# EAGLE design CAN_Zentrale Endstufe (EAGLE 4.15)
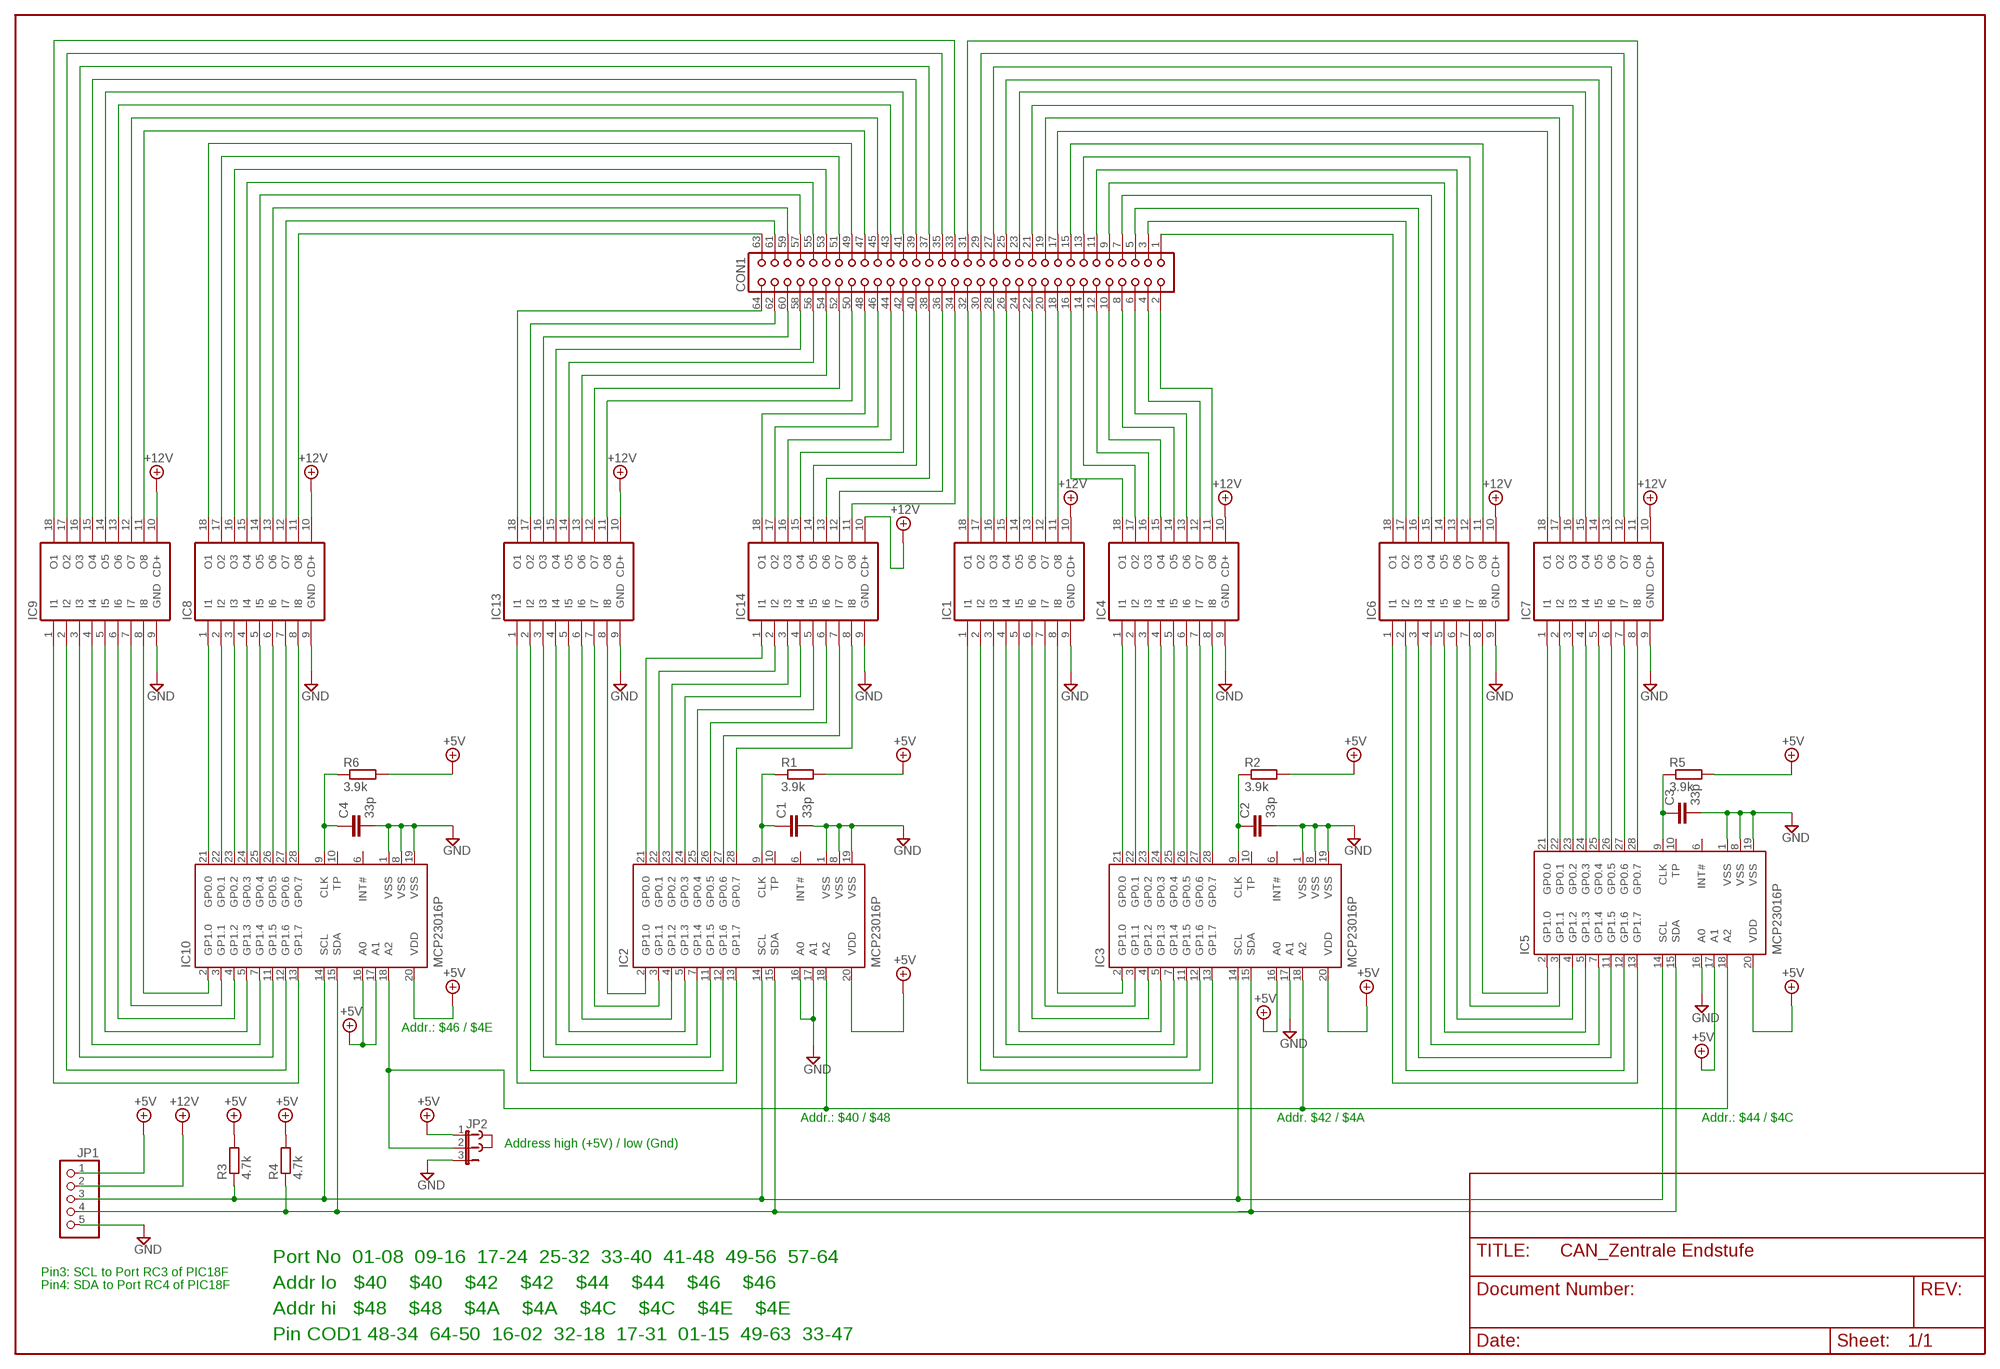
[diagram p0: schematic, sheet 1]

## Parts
C1  33p  C-EU025-025X050  [C025-025X050]
C2  33p  C-EU025-025X050  [C025-025X050]
C3  33p  C-EU025-025X050  [C025-025X050]
C4  33p  C-EU025-025X050  [C025-025X050]
CON1  CON64  [CON64]
IC1  ULN2803A  [DIL18]
IC2  MCP23016P  [DIL28-3]
IC3  MCP23016P  [DIL28-3]
IC4  ULN2803A  [DIL18]
IC5  MCP23016P  [DIL28-3]
IC6  ULN2803A  [DIL18]
IC7  ULN2803A  [DIL18]
IC8  ULN2803A  [DIL18]
IC9  ULN2803A  [DIL18]
IC10  MCP23016P  [DIL28-3]
IC13  ULN2803A  [DIL18]
IC14  ULN2803A  [DIL18]
J2  JUMPER  [JUMP]
JP1  PINHD-1X5  [1X05]
JP2  JP2E  [JP2]
R1  3.9k  R-EU_0204/7  [0204/7]
R2  3.9k  R-EU_0204/7  [0204/7]
R3  4.7k  R-EU_0204/7  [0204/7]
R4  4.7k  R-EU_0204/7  [0204/7]
R5  3.9k  R-EU_0204/7  [0204/7]
R6  3.9k  R-EU_0204/7  [0204/7]

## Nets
+5V: IC2.20(VDD) IC3.16(A0) IC3.20(VDD) IC5.17(A1) IC5.20(VDD) IC10.16(A0) IC10.17(A1) IC10.20(VDD) JP1.1 JP2.1 R1.2 R2.2 R3.2 R4.2 R5.2 R6.2
+12V: IC1.10(CD+) IC4.10(CD+) IC6.10(CD+) IC7.10(CD+) IC8.10(CD+) IC9.10(CD+) IC13.10(CD+) IC14.10(CD+) JP1.2
GND: C1.2 C2.2 C3.2 C4.2 IC1.9(GND) IC2.1(VSS) IC2.8(VSS) IC2.16(A0) IC2.17(A1) IC2.19(VSS) IC3.1(VSS) IC3.8(VSS) IC3.17(A1) IC3.19(VSS) IC4.9(GND) IC5.1(VSS) IC5.8(VSS) IC5.16(A0) IC5.19(VSS) IC6.9(GND) IC7.9(GND) IC8.9(GND) IC9.9(GND) IC10.1(VSS) IC10.8(VSS) IC10.19(VSS) IC13.9(GND) IC14.9(GND) JP1.5 JP2.3
N$1: IC2.28(GP0.7) IC14.8(I8)
N$2: IC2.27(GP0.6) IC14.7(I7)
N$3: IC2.26(GP0.5) IC14.6(I6)
N$4: IC2.25(GP0.4) IC14.5(I5)
N$5: IC2.24(GP0.3) IC14.4(I4)
N$6: IC2.23(GP0.2) IC14.3(I3)
N$7: IC2.22(GP0.1) IC14.2(I2)
N$8: C1.1 IC2.9(CLK) R1.1
N$9: IC2.21(GP0.0) IC14.1(I1)
N$10: IC2.2(GP1.0) IC13.8(I8)
N$11: IC2.3(GP1.1) IC13.7(I7)
N$12: IC2.4(GP1.2) IC13.6(I6)
N$13: IC2.5(GP1.3) IC13.5(I5)
N$14 [thick]: CON1.32 IC1.18(O1)
N$15: IC2.11(GP1.5) IC13.3(I3)
N$16: IC2.12(GP1.6) IC13.2(I2)
N$17: IC2.13(GP1.7) IC13.1(I1)
N$18 [thick]: CON1.50 IC13.11(O8)
N$19: IC2.15(SDA) IC3.15(SDA) IC5.15(SDA) IC10.15(SDA) JP1.4 R4.1
N$20 [thick]: CON1.52 IC13.12(O7)
N$21: IC2.14(SCL) IC3.14(SCL) IC5.14(SCL) IC10.14(SCL) JP1.3 R3.1
N$22 [thick]: CON1.54 IC13.13(O6)
N$23 [thick]: CON1.56 IC13.14(O5)
N$24 [thick]: CON1.58 IC13.15(O4)
N$25 [thick]: CON1.60 IC13.16(O3)
N$26 [thick]: CON1.62 IC13.17(O2)
N$27 [thick]: CON1.64 IC13.18(O1)
N$28 [thick]: CON1.48 IC14.18(O1)
N$29 [thick]: CON1.46 IC14.17(O2)
N$30 [thick]: CON1.44 IC14.16(O3)
N$31 [thick]: CON1.42 IC14.15(O4)
N$32 [thick]: CON1.40 IC14.14(O5)
N$33 [thick]: CON1.38 IC14.13(O6)
N$34 [thick]: CON1.36 IC14.12(O7)
N$35 [thick]: CON1.34 IC14.11(O8)
N$36 [thick]: CON1.30 IC1.17(O2)
N$37 [thick]: CON1.28 IC1.16(O3)
N$38 [thick]: CON1.26 IC1.15(O4)
N$39 [thick]: CON1.24 IC1.14(O5)
N$40 [thick]: CON1.22 IC1.13(O6)
N$41 [thick]: CON1.20 IC1.12(O7)
N$42 [thick]: CON1.18 IC1.11(O8)
N$43: IC5.21(GP0.0) IC7.1(I1)
N$44 [thick]: CON1.16 IC4.18(O1)
N$45 [thick]: CON1.14 IC4.17(O2)
N$46 [thick]: CON1.12 IC4.16(O3)
N$47 [thick]: CON1.10 IC4.15(O4)
N$48 [thick]: CON1.8 IC4.14(O5)
N$49 [thick]: CON1.6 IC4.13(O6)
N$50 [thick]: CON1.4 IC4.12(O7)
N$51 [thick]: CON1.2 IC4.11(O8)
N$52: IC3.21(GP0.0) IC4.1(I1)
N$53: IC3.22(GP0.1) IC4.2(I2)
N$54: IC3.23(GP0.2) IC4.3(I3)
N$55: IC3.24(GP0.3) IC4.4(I4)
N$56: IC3.25(GP0.4) IC4.5(I5)
N$57: IC3.26(GP0.5) IC4.6(I6)
N$58: IC3.27(GP0.6) IC4.7(I7)
N$59: IC3.28(GP0.7) IC4.8(I8)
N$60: IC1.8(I8) IC3.2(GP1.0)
N$61: IC1.7(I7) IC3.3(GP1.1)
N$62: IC1.6(I6) IC3.4(GP1.2)
N$63: IC1.5(I5) IC3.5(GP1.3)
N$64: IC1.4(I4) IC3.7(GP1.4)
N$65: IC1.3(I3) IC3.11(GP1.5)
N$66: IC1.2(I2) IC3.12(GP1.6)
N$67: IC1.1(I1) IC3.13(GP1.7)
N$68: C2.1 IC3.9(CLK) R2.1
N$69: IC5.22(GP0.1) IC7.2(I2)
N$70: IC2.7(GP1.4) IC13.4(I4)
N$71: IC5.23(GP0.2) IC7.3(I3)
N$72: IC5.24(GP0.3) IC7.4(I4)
N$73: IC5.25(GP0.4) IC7.5(I5)
N$74: IC5.26(GP0.5) IC7.6(I6)
N$75: IC5.27(GP0.6) IC7.7(I7)
N$76: IC5.28(GP0.7) IC7.8(I8)
N$77: IC5.2(GP1.0) IC6.8(I8)
N$78: IC5.3(GP1.1) IC6.7(I7)
N$79: IC5.4(GP1.2) IC6.6(I6)
N$80: IC5.5(GP1.3) IC6.5(I5)
N$81: IC5.7(GP1.4) IC6.4(I4)
N$82: IC5.11(GP1.5) IC6.3(I3)
N$83: IC5.12(GP1.6) IC6.2(I2)
N$84: IC5.13(GP1.7) IC6.1(I1)
N$85 [thick]: CON1.1 IC6.18(O1)
N$86 [thick]: CON1.3 IC6.17(O2)
N$87: C3.1 IC5.9(CLK) R5.1
N$88 [thick]: CON1.5 IC6.16(O3)
N$89 [thick]: CON1.7 IC6.15(O4)
N$90 [thick]: CON1.9 IC6.14(O5)
N$91 [thick]: CON1.11 IC6.13(O6)
N$92 [thick]: CON1.13 IC6.12(O7)
N$93 [thick]: CON1.15 IC6.11(O8)
N$94 [thick]: CON1.17 IC7.18(O1)
N$95 [thick]: CON1.19 IC7.17(O2)
N$96 [thick]: CON1.21 IC7.16(O3)
N$97 [thick]: CON1.23 IC7.15(O4)
N$98 [thick]: CON1.25 IC7.14(O5)
N$99 [thick]: CON1.27 IC7.13(O6)
N$100 [thick]: CON1.29 IC7.12(O7)
N$101 [thick]: CON1.31 IC7.11(O8)
N$102: IC8.1(I1) IC10.21(GP0.0)
N$103: IC8.2(I2) IC10.22(GP0.1)
N$104: IC8.3(I3) IC10.23(GP0.2)
N$105: IC8.4(I4) IC10.24(GP0.3)
N$106: IC2.18(A2) IC3.18(A2) IC5.18(A2) IC10.18(A2) JP2.2
N$107: IC8.6(I6) IC10.26(GP0.5)
N$108: IC8.7(I7) IC10.27(GP0.6)
N$109: IC8.8(I8) IC10.28(GP0.7)
N$110: IC9.8(I8) IC10.2(GP1.0)
N$111: IC9.7(I7) IC10.3(GP1.1)
N$112: IC9.6(I6) IC10.4(GP1.2)
N$113: IC9.5(I5) IC10.5(GP1.3)
N$114: IC9.4(I4) IC10.7(GP1.4)
N$115: IC9.3(I3) IC10.11(GP1.5)
N$116: IC9.2(I2) IC10.12(GP1.6)
N$117: IC9.1(I1) IC10.13(GP1.7)
N$118 [thick]: CON1.63 IC8.11(O8)
N$119 [thick]: CON1.61 IC8.12(O7)
N$120 [thick]: CON1.59 IC8.13(O6)
N$121 [thick]: CON1.57 IC8.14(O5)
N$122 [thick]: CON1.55 IC8.15(O4)
N$123 [thick]: CON1.53 IC8.16(O3)
N$124 [thick]: CON1.51 IC8.17(O2)
N$125 [thick]: CON1.49 IC8.18(O1)
N$126 [thick]: CON1.47 IC9.11(O8)
N$127 [thick]: CON1.45 IC9.12(O7)
N$128 [thick]: CON1.43 IC9.13(O6)
N$129 [thick]: CON1.41 IC9.14(O5)
N$130 [thick]: CON1.39 IC9.15(O4)
N$131 [thick]: CON1.37 IC9.16(O3)
N$132 [thick]: CON1.35 IC9.17(O2)
N$133 [thick]: CON1.33 IC9.18(O1)
N$134: C4.1 IC10.9(CLK) R6.1
N$135: IC8.5(I5) IC10.25(GP0.4)
Unconnected: IC2.6(INT#) IC2.10(TP) IC3.6(INT#) IC3.10(TP) IC5.6(INT#) IC5.10(TP) IC10.6(INT#) IC10.10(TP)

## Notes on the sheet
- Addr.: $46 / $4E
- Addr.: $40 / $48 | Addr. $42 / $4A | Addr.: $44 / $4C
- Address high (+5V) / low (Gnd)
- Port No  01-08  09-16  17-24  25-32  33-40  41-48  49-56  57-64
- Pin3: SCL to Port RC3 of PIC18F
- Pin4: SDA to Port RC4 of PIC18F | Addr lo   $40    $40    $42    $42    $44    $44    $46    $46
- Addr hi   $48    $48    $4A    $4A    $4C    $4C    $4E    $4E
- Pin COD1 48-34  64-50  16-02  32-18  17-31  01-15  49-63  33-47

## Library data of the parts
C1-C4 = rcl:C-EU: CAPACITOR, European symbol
CON1 = con-harting:CON64: CONNECTOR
IC1 IC4 IC6-IC9 IC13 IC14 = uln-udn:ULN2803A: DRIVER ARRAY
IC2 IC3 IC5 IC10 = microchip-dspic:MCP23016: 16-Bit I/O Expander with I2C Interface
J2 = jumper:JUMPER: JUMPER header
JP1 = pinhead:PINHD-1X5: PIN HEADER
JP2 = jumper:JP2E: JUMPER
R1-R6 = rcl:R-EU_: RESISTOR, European symbol

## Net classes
1 thick: width 0.889 mm

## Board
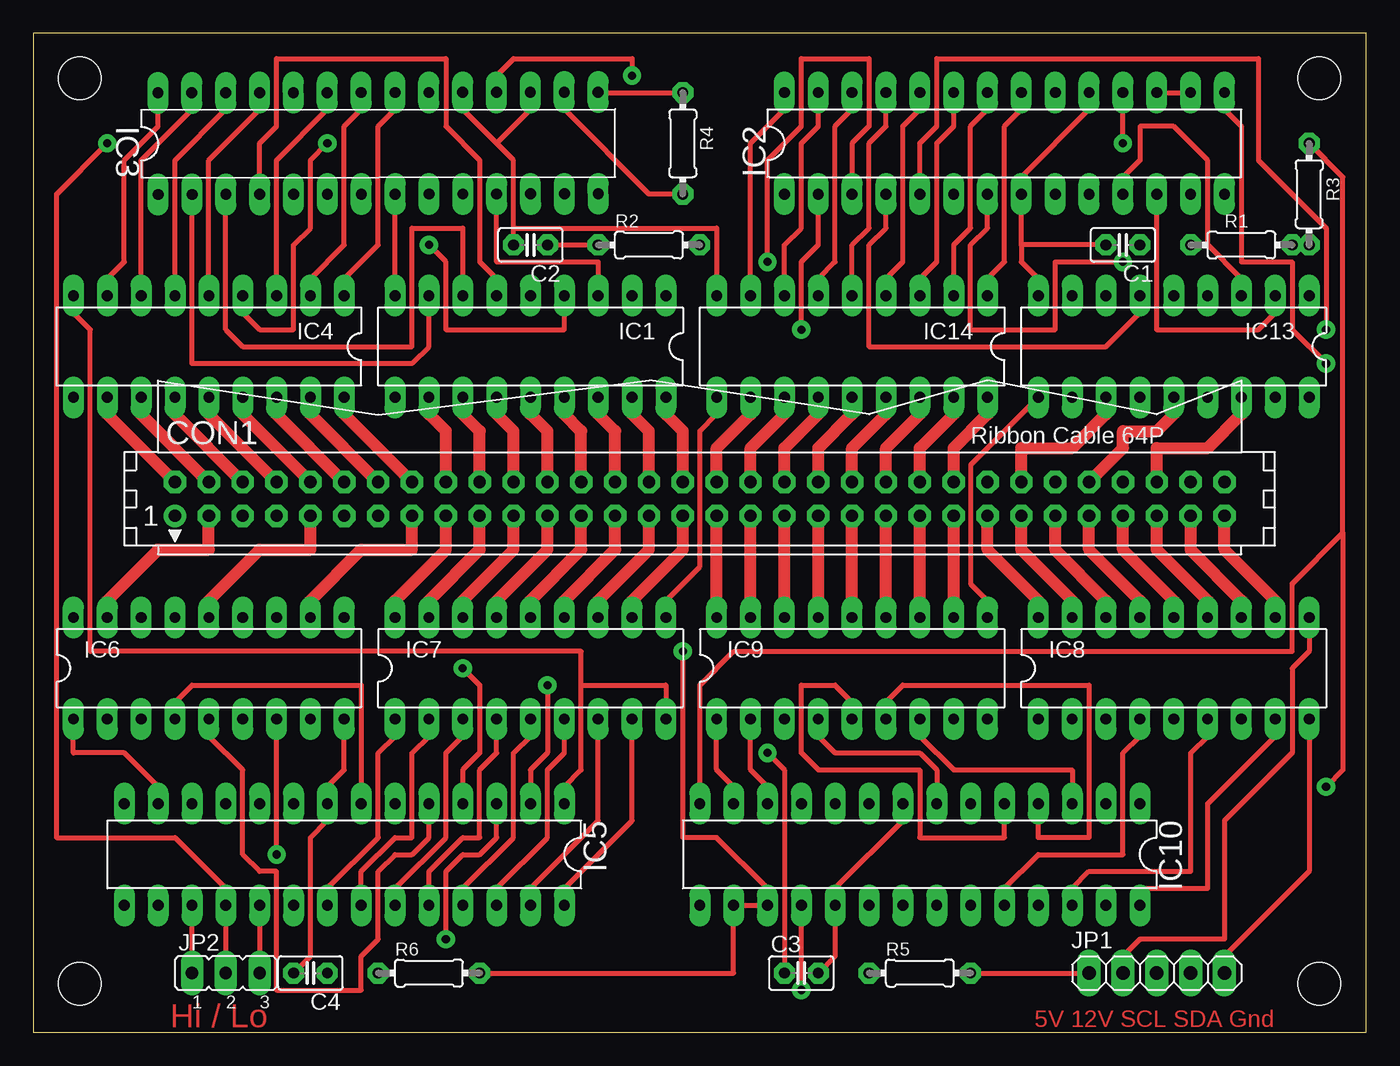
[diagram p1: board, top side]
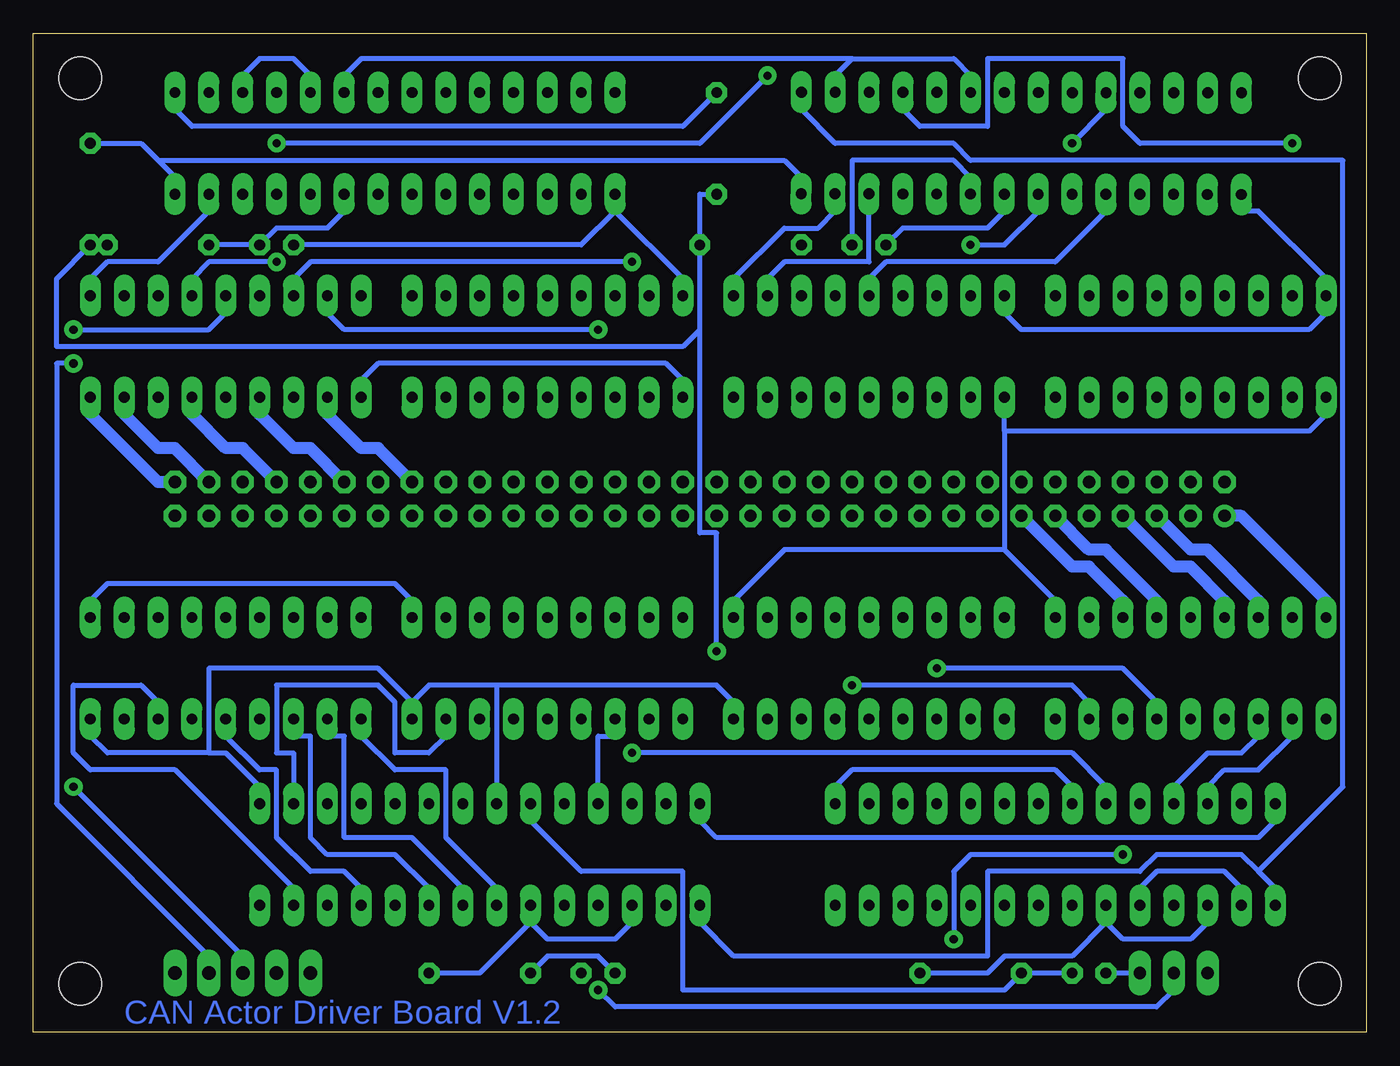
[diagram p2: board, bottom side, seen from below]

Size 100 x 74.92 mm. Coordinates in mm from the lower left corner, seen from the top.
Outline: 0,0 100,0 100,74.92 0,74.92 0,0
Copper layers (1*16): Top 0.035mm / dielectric 1.5mm / Bottom 0.035mm
Design rules "default": minimum track width 15mil, minimum drill 24mil, track to track 8mil, track to pad 8mil, pad to pad 8mil, via to via 8mil, smd to smd 8mil, copper to edge 40mil, drill to drill 8mil, minimum pad ring 15mil, minimum via ring 15mil, stop-mask expansion 4mil, vias tented up to drill 0mil, thermal gap 10mil
Holes 3.2 mm at 3.47,71.55 96.47,71.55 3.47,3.63 96.47,3.63
tRestrict: area 0.5,67.9 to 6.8,74.3; area 93.2,0.6 to 99.5,7; area 93.2,67.9 to 99.5,74.3; area 0.5,0.6 to 6.8,7
bRestrict: area 0.5,67.9 to 6.8,74.3; area 0.5,0.6 to 6.8,7; area 93.2,0.6 to 99.5,7; area 93.2,67.9 to 99.5,74.3
vRestrict: area 9.4,37.5 to 90.6,42.5

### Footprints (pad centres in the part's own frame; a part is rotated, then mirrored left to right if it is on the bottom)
C025-025X050 = drill 0.813 octagon: 1 -1.27,0; 2 1.27,0
CON64 = drill 0.914 round: 1 -39.37,-1.27 | drill 0.914 octagon: 2 -39.37,1.27; 3 -36.83,-1.27; 4 -36.83,1.27; 5 -34.29,-1.27; 6 -34.29,1.27; 7 -31.75,-1.27; 8 -31.75,1.27; 9 -29.21,-1.27; 10 -29.21,1.27; 11 -26.67,-1.27; 12 -26.67,1.27; 13 -24.13,-1.27; 14 -24.13,1.27; 15 -21.59,-1.27; 16 -21.59,1.27; 17 -19.05,-1.27; 18 -19.05,1.27; 19 -16.51,-1.27; 20 -16.51,1.27; 21 -13.97,-1.27; 22 -13.97,1.27; 23 -11.43,-1.27; 24 -11.43,1.27; 25 -8.89,-1.27; 26 -8.89,1.27; 27 -6.35,-1.27; 28 -6.35,1.27; 29 -3.81,-1.27; 30 -3.81,1.27; 31 -1.27,-1.27; 32 -1.27,1.27; 33 1.27,-1.27; 34 1.27,1.27; 35 3.81,-1.27; 36 3.81,1.27; 37 6.35,-1.27; 38 6.35,1.27; 39 8.89,-1.27; 40 8.89,1.27; 41 11.43,-1.27; 42 11.43,1.27; 43 13.97,-1.27; 44 13.97,1.27; 45 16.51,-1.27; 46 16.51,1.27; 47 19.05,-1.27; 48 19.05,1.27; 49 21.59,-1.27; 50 21.59,1.27; 51 24.13,-1.27; 52 24.13,1.27; 53 26.67,-1.27; 54 26.67,1.27; 55 29.21,-1.27; 56 29.21,1.27; 57 31.75,-1.27; 58 31.75,1.27; 59 34.29,-1.27; 60 34.29,1.27; 61 36.83,-1.27; 62 36.83,1.27; 63 39.37,-1.27; 64 39.37,1.27
DIL18 = drill 0.813 long: 1 -10.16,-3.81; 2 -7.62,-3.81; 3 -5.08,-3.81; 4 -2.54,-3.81; 5 0,-3.81; 6 2.54,-3.81; 7 5.08,-3.81; 8 7.62,-3.81; 9 10.16,-3.81; 10 10.16,3.81; 11 7.62,3.81; 12 5.08,3.81; 13 2.54,3.81; 14 0,3.81; 15 -2.54,3.81; 16 -5.08,3.81; 17 -7.62,3.81; 18 -10.16,3.81
DIL28-3 = drill 0.813 long: 1 -16.51,-3.81; 2 -13.97,-3.81; 3 -11.43,-3.81; 4 -8.89,-3.81; 5 -6.35,-3.81; 6 -3.81,-3.81; 7 -1.27,-3.81; 8 1.27,-3.81; 9 3.81,-3.81; 10 6.35,-3.81; 11 8.89,-3.81; 12 11.43,-3.81; 13 13.97,-3.81; 14 16.51,-3.81; 15 16.51,3.81; 16 13.97,3.81; 17 11.43,3.81; 18 8.89,3.81; 19 6.35,3.81; 20 3.81,3.81; 21 1.27,3.81; 22 -1.27,3.81; 23 -3.81,3.81; 24 -6.35,3.81; 25 -8.89,3.81; 26 -11.43,3.81; 27 -13.97,3.81; 28 -16.51,3.81
1X05 = drill 1.016 long: 1 -5.08,0; 2 -2.54,0; 3 0,0; 4 2.54,0; 5 5.08,0
JP2 = drill 0.914 long: 1 -2.54,0; 2 0,0; 3 2.54,0
0204/7 = drill 0.813 octagon: 1 -3.81,0; 2 3.81,0

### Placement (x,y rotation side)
C1  81.75,59.05 180 top
C2  37.3,59.05 180 top
C3  57.62,4.44 0 top
C4  20.79,4.44 180 top
CON1  50,40 0 top
IC1  37.3,51.43 180 top
IC2  72.86,66.67 0 top
IC3  25.87,66.67 0.1 top
IC4  13.17,51.43 180 top
IC5  23.33,13.33 180 top
IC6  13.17,27.3 0 top
IC7  37.3,27.3 0 top
IC8  85.56,27.3 0 top
IC9  61.43,27.3 0 top
IC10  66.51,13.33 180 top
IC13  85.56,51.43 180 top
IC14  61.43,51.43 180 top
J2  not placed on the board
JP1  84.29,4.44 0 top
JP2  14.44,4.44 0 top
R1  90.64,59.05 0 top
R2  46.19,59.05 0 top
R3  95.72,62.86 270 top
R4  48.73,66.67 270 top
R5  66.51,4.44 0 top
R6  29.68,4.44 0 top

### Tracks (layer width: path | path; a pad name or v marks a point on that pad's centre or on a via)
+5V  (via drill 0.61)
  Top 0.381: R5.2 JP1.1 | JP2.1 IC5.17 | R6.2 52.54,4.44 IC10.16 IC10.17 55.08,10.79 51.27,14.6 48.73,14.6 v48.73,28.57 | R3.2 R1.2 | R4.2 46.19,62.86 39.84,69.21 IC3.16
  Bottom 0.381: 62.7,8.25 66.51,4.44 R5.2 | 19.52,8.25 18.25,6.98 13.17,6.98 11.9,8.25 IC5.17 | 19.52,8.25 22.06,5.71 27.14,5.71 28.41,4.44 R6.2 | 19.52,8.25 IC5.20 | 62.7,8.25 61.43,6.98 56.35,6.98 55.08,8.25 IC10.17 | 62.7,8.25 IC10.20 | 38.57,73.02 30.95,73.02 29.68,71.75 IC3.20 | 38.57,73.02 39.84,71.75 IC3.16 | 38.57,73.02 75.4,73.02 76.67,71.75 IC2.20 | R4.2 50,62.86 R2.2 50,52.7 | R3.2 98.26,56.51 98.26,51.43 51.27,51.43 50,52.7 | v48.73,28.57 48.73,37.46 50,37.46 50,52.7
+12V
  Top 0.381: IC14.10 51.27,46.35 50,45.08 50,34.92 47.46,32.38 IC7.10 | IC13.10 70.32,42.54 70.32,33.65 71.59,32.38 IC9.10 | JP1.2 81.75,5.71 83.02,6.98 89.37,6.98 89.37,15.87 94.45,20.95 94.45,27.3 95.72,28.57 IC8.10
  Bottom 0.381: 27.14,36.19 23.33,32.38 IC6.10 | 27.14,45.08 27.14,36.19 | 27.14,45.08 IC1.10 | 27.14,36.19 43.65,36.19 47.46,32.38 IC7.10 | 27.14,45.08 4.28,45.08 3.01,46.35 IC4.10 | IC8.10 95.72,32.38 94.45,33.65 72.86,33.65 71.59,32.38 IC9.10 | IC14.10 51.27,48.89 52.54,50.16 74.13,50.16 75.4,48.89 IC13.10
GND
  Top 0.381: IC1.9 27.14,61.59 IC3.8 | 34.76,66.67 36.03,65.4 36.03,60.32 | 34.76,66.67 32.22,69.21 IC3.19 | C2.2 36.03,60.32 | 34.76,66.67 37.3,69.21 IC3.17 | IC2.17 IC2.16 | 74.13,59.05 74.13,57.78 75.4,56.51 IC13.9 | 74.13,59.05 IC2.8 74.13,64.13 79.21,69.21 IC2.19 | C1.2 74.13,59.05 | 36.03,60.32 51.27,60.32 IC14.9 | IC5.19 JP2.3 | IC6.9 23.33,19.68 22.06,18.41 IC5.8 22.06,15.87 20.79,14.6 20.79,5.71 C4.2 | JP1.5 89.37,5.71 95.72,12.06 IC8.9 | C3.2 60.16,5.71 IC10.19 60.16,10.79 65.24,15.87 IC10.8 | 41.11,26.03 41.11,19.68 39.84,18.41 IC5.1 | 41.11,26.03 47.46,26.03 IC7.9 | 41.11,26.03 41.11,28.57 4.28,28.57 4.28,52.7 3.01,53.97 IC4.9
  Bottom 0.381: IC3.1 9.36,61.59 8.09,61.59 3.01,56.51 IC4.9 3.01,53.97 4.28,52.7 25.87,52.7 27.14,53.97 IC1.9 | C2.2 34.76,60.32 28.41,60.32 27.14,61.59 IC3.8 | 56.35,61.59 51.27,56.51 IC14.9 | IC2.17 84.29,71.75 83.02,73.02 80.48,73.02 79.21,71.75 IC2.19 | 56.35,61.59 58.89,59.05 C1.2 | 56.35,61.59 IC2.1 | JP2.3 C4.2 | IC5.16 9.36,10.79 10.63,12.06 15.71,12.06 16.98,10.79 IC5.19 | IC5.1 39.84,18.41 38.57,19.68 23.33,19.68 22.06,18.41 IC5.8 | 86.83,20.95 94.45,20.95 95.72,22.22 IC8.9 | 86.83,20.95 85.56,20.95 83.02,18.41 IC10.1 | 65.24,26.03 70.32,26.03 71.59,24.76 | 65.24,26.03 48.73,26.03 47.46,24.76 IC7.9 | 65.24,26.03 IC10.8 | 86.83,20.95 86.83,27.3 74.13,27.3 71.59,24.76 | 71.59,24.76 IC9.9
N$1
  Top 0.381: IC14.8 53.81,66.67 56.35,69.21 IC2.28
N$2
  Top 0.381: IC14.7 56.35,59.05 57.62,60.32 57.62,66.67 58.89,67.94 IC2.27
N$3
  Top 0.381: IC14.6 58.89,56.51 60.16,57.78 60.16,67.94 61.43,69.21 IC2.26
N$4
  Top 0.381: IC14.5 61.43,59.05 62.7,60.32 62.7,66.67 63.97,67.94 IC2.25
N$5
  Top 0.381: IC14.4 63.97,56.51 65.24,57.78 65.24,67.94 66.51,69.21 IC2.24
N$6
  Top 0.381: IC14.3 66.51,56.51 67.78,57.78 67.78,66.67 69.05,67.94 IC2.23
N$7
  Top 0.381: IC14.2 69.05,59.05 70.32,60.32 70.32,67.94 71.59,69.21 IC2.22
N$8
  Bottom 0.381: R1.1 C1.1 81.75,60.32 77.94,60.32 76.67,61.59 IC2.9
N$9
  Top 0.381: IC14.1 71.59,56.51 72.86,57.78 72.86,67.94 74.13,69.21 IC2.21
N$10  (via drill 0.61)
  Top 0.381: v57.62,52.7 57.62,57.78 58.89,59.05 IC2.2
  Bottom 0.381: v57.62,52.7 76.67,52.7 77.94,53.97 IC13.8
N$11  (via drill 0.61)
  Top 0.381: v55.08,57.78 55.08,65.4 57.62,67.94 57.62,73.02 62.7,73.02 62.7,67.94 61.43,66.67 IC2.3
  Bottom 0.381: v55.08,57.78 79.21,57.78 80.48,56.51 IC13.7
N$12
  Top 0.381: IC13.6 83.02,53.97 80.48,51.43 62.7,51.43 62.7,59.05 63.97,60.32 IC2.4
N$13  (via drill 0.61)
  Top 0.381: v96.99,52.7 96.99,60.32 91.91,65.4 91.91,73.02 67.78,73.02 67.78,67.94 66.51,66.67 IC2.5
  Bottom 0.381: v96.99,52.7 86.83,52.7 85.56,53.97 IC13.5
N$14
  Top 0.889: CON1.32 48.73,45.08 47.46,46.35 IC1.18
N$15
  Top 0.381: IC13.3 90.64,56.51 88.1,59.05 88.1,65.4 85.56,67.94 83.02,67.94 83.02,65.4 81.75,64.13 IC2.11
N$16
  Top 0.381: IC13.2 93.18,53.97 91.91,52.7 84.29,52.7 IC2.12
N$17
  Bottom 0.381: IC2.13 86.83,61.59 90.64,57.78 94.45,57.78 95.72,56.51 IC13.1
N$18
  Bottom 0.889: CON1.50 74.13,43.81 75.4,43.81 77.94,46.35 IC13.11
N$19  (via drill 0.61)
  Top 0.381: R4.1 42.38,70.48 IC3.15 | v96.99,50.16 94.45,52.7 94.45,57.78 90.64,57.78 90.64,67.94 89.37,69.21 IC2.15
  Bottom 0.381: 8.09,12.06 9.36,13.33 15.71,13.33 16.98,12.06 28.41,12.06 28.41,5.71 47.46,5.71 50,8.25 IC10.15 | 8.09,12.06 6.82,10.79 IC5.15 | R4.1 51.27,67.94 88.1,67.94 89.37,69.21 IC2.15 | v96.99,50.16 98.26,50.16 98.26,17.14 86.83,5.71 JP1.4 | 8.09,12.06 1.74,18.41 1.74,65.4 29.68,65.4 30.95,66.67 39.84,66.67 42.38,69.21 IC3.15
N$20
  Top 0.889: CON1.52 74.13,43.81 77.94,43.81 80.48,46.35 IC13.12
N$21  (via drill 0.61)
  Top 0.381: v96.99,18.41 98.26,19.68 98.26,37.46 | 98.26,37.46 98.26,64.13 R3.1 | 98.26,37.46 94.45,33.65 94.45,28.57 52.54,28.57 50,26.03 IC10.14
  Bottom 0.381: IC5.14 6.82,15.87 8.09,14.6 48.73,14.6 50,15.87 IC10.14 | 90.64,65.4 91.91,66.67 R3.1 | 90.64,65.4 89.37,64.13 IC2.14 | 90.64,65.4 43.65,65.4 42.38,64.13 IC3.14 | v96.99,18.41 84.29,5.71 JP1.3
N$22
  Bottom 0.889: CON1.54 79.21,43.81 80.48,43.81 83.02,46.35 IC13.13
N$23
  Top 0.889: CON1.56 81.75,43.81 81.75,45.08 84.29,45.08 85.56,46.35 IC13.14
N$24
  Bottom 0.889: CON1.58 84.29,43.81 85.56,43.81 88.1,46.35 IC13.15
N$25
  Top 0.889: CON1.60 84.29,43.81 88.1,43.81 90.64,46.35 IC13.16
N$26
  Bottom 0.889: CON1.62 89.37,43.81 90.64,43.81 93.18,46.35 IC13.17
N$27
  Bottom 0.889: CON1.64 90.64,41.27 95.72,46.35 IC13.18
N$28
  Top 0.889: CON1.48 69.05,43.81 71.59,46.35 IC14.18
N$29
  Top 0.889: CON1.46 66.51,43.81 69.05,46.35 IC14.17
N$30
  Top 0.889: CON1.44 63.97,43.81 66.51,46.35 IC14.16
N$31
  Top 0.889: CON1.42 61.43,43.81 63.97,46.35 IC14.15
N$32
  Top 0.889: CON1.40 58.89,43.81 61.43,46.35 IC14.14
N$33
  Top 0.889: CON1.38 56.35,43.81 58.89,46.35 IC14.13
N$34
  Top 0.889: CON1.36 53.81,43.81 56.35,46.35 IC14.12
N$35
  Top 0.889: CON1.34 51.27,43.81 53.81,46.35 IC14.11
N$36
  Top 0.889: CON1.30 46.19,45.08 44.92,46.35 IC1.17
N$37
  Top 0.889: CON1.28 43.65,45.08 42.38,46.35 IC1.16
N$38
  Top 0.889: CON1.26 41.11,45.08 39.84,46.35 IC1.15
N$39
  Top 0.889: CON1.24 38.57,45.08 37.3,46.35 IC1.14
N$40
  Top 0.889: CON1.22 36.03,45.08 34.76,46.35 IC1.13
N$41
  Top 0.889: CON1.20 33.49,45.08 32.22,46.35 IC1.12
N$42
  Top 0.889: CON1.18 30.95,45.08 29.68,46.35 IC1.11
N$43
  Top 0.381: IC5.21 22.06,10.79 25.87,14.6 25.87,20.95 27.14,22.22 IC7.1
N$44
  Top 0.889: CON1.16 23.33,46.35 IC4.18
N$45
  Top 0.889: CON1.14 20.79,46.35 IC4.17
N$46
  Top 0.889: CON1.12 18.25,46.35 IC4.16
N$47
  Top 0.889: CON1.10 15.71,46.35 IC4.15
N$48
  Top 0.889: CON1.8 13.17,46.35 IC4.14
N$49
  Top 0.889: CON1.6 10.63,46.35 IC4.13
N$50
  Top 0.889: CON1.4 8.09,46.35 IC4.12
N$51
  Top 0.889: CON1.2 5.55,46.35 IC4.11
N$52
  Top 0.381: IC4.1 23.33,56.51 25.87,59.05 25.87,67.94 27.14,69.21 IC3.21
N$53
  Top 0.381: IC4.2 20.79,56.51 23.33,59.05 23.33,67.94 24.6,69.21 IC3.22
N$54
  Top 0.381: IC4.3 18.25,65.4 22.06,69.21 IC3.23
N$55  (via drill 0.61)
  Top 0.381: v22.06,66.67 20.79,65.4 20.79,60.32 19.52,59.05 19.52,52.7 16.98,52.7 15.71,53.97 IC4.4
  Bottom 0.381: v22.06,66.67 19.52,69.21 IC3.24
N$56
  Top 0.381: IC4.5 13.17,65.4 16.98,69.21 IC3.25
N$57
  Top 0.381: IC4.6 10.63,65.4 14.44,69.21 IC3.26
N$58
  Top 0.381: IC4.7 8.09,65.4 11.9,69.21 IC3.27
N$59
  Top 0.381: IC4.8 5.55,56.51 6.82,57.78 6.82,65.4 9.36,67.94 9.36,69.21 IC3.28
N$60
  Top 0.381: IC1.8 29.68,51.43 28.41,50.16 11.9,50.16 11.9,61.59 IC3.2
N$61
  Top 0.381: IC3.3 14.44,61.59 14.44,52.7 15.71,51.43 28.41,51.43 28.41,60.32 32.22,60.32 IC1.7
N$62
  Top 0.381: IC3.4 16.98,64.13 16.98,66.67 18.25,67.94 18.25,73.02 30.95,73.02 30.95,67.94 33.49,65.4 33.49,57.78 34.76,56.51 IC1.6
N$63
  Bottom 0.381: IC1.5 37.3,56.51 36.03,57.78 23.33,57.78 19.52,61.59 IC3.5
N$64  (via drill 0.61)
  Top 0.381: v29.68,59.05 30.95,57.78 30.95,52.7 39.84,52.7 IC1.4
  Bottom 0.381: v29.68,59.05 27.14,59.05 24.6,61.59 IC3.7
N$65
  Top 0.381: IC3.11 34.76,61.59 34.76,57.78 42.38,57.78 IC1.3
N$66
  Bottom 0.381: IC1.2 44.92,56.51 43.65,57.78 37.3,57.78 37.3,61.59 IC3.12
N$67
  Bottom 0.381: IC1.1 47.46,56.51 43.65,60.32 41.11,60.32 39.84,61.59 IC3.13
N$68
  Top 0.381: C2.1 R2.1
  Bottom 0.381: C2.1 38.57,65.4 30.95,65.4 29.68,64.13 IC3.9
N$69
  Top 0.381: IC5.22 24.6,12.06 27.14,14.6 28.41,14.6 28.41,20.95 29.68,22.22 IC7.2
N$70  (via drill 0.61)
  Top 0.381: v81.75,57.78 76.67,57.78 76.67,52.7 70.32,52.7 70.32,59.05 71.59,60.32 IC2.7
  Bottom 0.381: v81.75,57.78 86.83,57.78 88.1,56.51 IC13.4
N$71
  Top 0.381: IC5.23 27.14,10.79 30.95,14.6 30.95,20.95 32.22,22.22 IC7.3
N$72
  Top 0.381: IC5.24 29.68,12.06 32.22,14.6 33.49,14.6 33.49,19.68 34.76,20.95 IC7.4
N$73
  Top 0.381: IC5.25 32.22,10.79 36.03,14.6 36.03,20.95 37.3,22.22 IC7.5
N$74
  Top 0.381: IC5.26 34.76,10.79 38.57,14.6 38.57,19.68 39.84,20.95 IC7.6
N$75
  Top 0.381: IC5.27 37.3,10.79 42.38,15.87 IC7.7
N$76
  Top 0.381: IC5.28 39.84,10.79 44.92,15.87 IC7.8
N$77  (via drill 0.61)
  Top 0.381: v38.57,26.03 38.57,20.95 37.3,19.68 IC5.2
  Bottom 0.381: v38.57,26.03 22.06,26.03 20.79,24.76 IC6.8
N$78  (via drill 0.61)
  Top 0.381: v30.95,6.98 30.95,12.06 32.22,13.33 33.49,13.33 34.76,14.6 IC5.3 | v18.25,13.33 IC6.7
  Bottom 0.381: v18.25,13.33 29.68,13.33 30.95,12.06 v30.95,6.98
N$79  (via drill 0.61)
  Top 0.381: v32.22,27.3 33.49,26.03 33.49,20.95 32.22,19.68 IC5.4
  Bottom 0.381: v32.22,27.3 18.25,27.3 15.71,24.76 IC6.6
N$80
  Top 0.381: IC6.5 13.17,22.22 15.71,19.68 15.71,13.33 16.98,12.06 18.25,12.06 18.25,3.17 24.6,3.17 24.6,5.71 25.87,6.98 25.87,12.06 27.14,13.33 28.41,13.33 29.68,14.6 IC5.5
N$81
  Top 0.381: IC6.4 10.63,24.76 11.9,26.03 24.6,26.03 IC5.7
N$82
  Bottom 0.381: IC5.11 14.44,18.41 11.9,20.95 9.36,20.95 8.09,22.22 IC6.3
N$83
  Bottom 0.381: IC5.12 11.9,18.41 10.63,19.68 8.09,19.68 5.55,22.22 IC6.2
N$84
  Top 0.381: IC5.13 9.36,18.41 6.82,20.95 3.01,20.95 IC6.1
N$85
  Bottom 0.889: CON1.1 9.36,38.73 3.01,32.38 IC6.18
N$86
  Top 0.889: CON1.3 13.17,36.19 9.36,36.19 5.55,32.38 IC6.17
N$87  (via drill 0.61)
  Top 0.381: v55.08,20.95 56.35,19.68 C3.1
  Bottom 0.381: v55.08,20.95 22.06,20.95 19.52,18.41 IC5.9 | R5.1 61.43,5.71 57.62,5.71 C3.1
N$88
  Bottom 0.889: CON1.5 13.17,36.19 11.9,36.19 8.09,32.38 IC6.16
N$89
  Bottom 0.889: CON1.7 14.44,34.92 13.17,34.92 10.63,32.38 IC6.15
N$90
  Top 0.889: CON1.9 20.79,36.19 16.98,36.19 13.17,32.38 IC6.14
N$91
  Bottom 0.889: CON1.11 20.79,36.19 19.52,36.19 15.71,32.38 IC6.13
N$92
  Bottom 0.889: CON1.13 22.06,34.92 20.79,34.92 18.25,32.38 IC6.12
N$93
  Top 0.889: CON1.15 28.41,36.19 24.6,36.19 20.79,32.38 IC6.11
N$94
  Top 0.889: CON1.17 30.95,36.19 27.14,32.38 IC7.18
N$95
  Top 0.889: CON1.19 33.49,36.19 29.68,32.38 IC7.17
N$96
  Top 0.889: CON1.21 36.03,36.19 32.22,32.38 IC7.16
N$97
  Top 0.889: CON1.23 38.57,36.19 34.76,32.38 IC7.15
N$98
  Top 0.889: CON1.25 41.11,36.19 37.3,32.38 IC7.14
N$99
  Top 0.889: CON1.27 43.65,36.19 39.84,32.38 IC7.13
N$100
  Top 0.889: CON1.29 46.19,36.19 42.38,32.38 IC7.12
N$101
  Top 0.889: CON1.31 48.73,36.19 44.92,32.38 IC7.11
N$102
  Bottom 0.381: IC10.21 65.24,10.79 69.05,14.6 69.05,19.68 72.86,19.68 75.4,22.22 IC8.1
N$103
  Bottom 0.381: IC10.22 67.78,10.79 71.59,14.6 76.67,14.6 76.67,22.22 77.94,22.22 IC8.2
N$104
  Bottom 0.381: IC10.23 70.32,10.79 72.86,13.33 77.94,13.33 79.21,14.6 79.21,22.22 80.48,22.22 IC8.3
N$105
  Top 0.381: IC10.24 72.86,10.79 75.4,13.33 81.75,13.33 81.75,20.95 83.02,22.22 IC8.4
N$106  (via drill 0.61)
  Top 0.381: JP2.2 IC5.18 14.44,10.79 10.63,14.6 1.74,14.6 1.74,62.86 v5.55,66.67 | v57.62,3.17 IC10.18 | v44.92,71.75 44.92,73.02 36.03,73.02 34.76,71.75 IC3.18 | v81.75,66.67 IC2.18
  Bottom 0.381: v57.62,3.17 56.35,1.9 15.71,1.9 14.44,3.17 JP2.2 | v44.92,71.75 50,66.67 v81.75,66.67 | v5.55,66.67 16.98,66.67 18.25,67.94 18.25,73.02 28.41,73.02 28.41,67.94 33.49,67.94 34.76,69.21 IC3.18
N$107
  Top 0.381: IC10.26 77.94,10.79 79.21,12.06 86.83,12.06 86.83,20.95 88.1,22.22 IC8.6
N$108
  Bottom 0.381: IC10.27 80.48,10.79 89.37,19.68 95.72,19.68 96.99,20.95 96.99,26.03 91.91,26.03 90.64,24.76 IC8.7
N$109
  Top 0.381: IC10.28 83.02,10.79 88.1,10.79 88.1,17.14 93.18,22.22 IC8.8
N$110
  Bottom 0.381: IC10.2 80.48,20.95 81.75,20.95 81.75,26.03 74.13,26.03 72.86,24.76 72.86,20.95 70.32,20.95 69.05,22.22 IC9.8
N$111
  Top 0.381: IC9.7 66.51,22.22 69.05,19.68 77.94,19.68 IC10.3
N$112
  Top 0.381: IC9.6 63.97,24.76 65.24,26.03 79.21,26.03 79.21,14.6 75.4,14.6 IC10.4
N$113
  Top 0.381: IC9.5 61.43,24.76 60.16,26.03 57.62,26.03 57.62,20.95 58.89,19.68 66.51,19.68 66.51,14.6 72.86,14.6 IC10.5
N$114
  Top 0.381: IC9.4 58.89,22.22 60.16,20.95 66.51,20.95 67.78,19.68 IC10.7
N$115
  Bottom 0.381: IC10.11 57.62,22.22 56.35,22.22 IC9.3
N$116
  Top 0.381: IC10.12 55.08,18.41 53.81,19.68 IC9.2
N$117
  Top 0.381: IC10.13 52.54,18.41 51.27,19.68 IC9.1
N$118
  Top 0.889: CON1.63 89.37,36.19 93.18,32.38 IC8.11
N$119
  Top 0.889: CON1.61 86.83,36.19 90.64,32.38 IC8.12
N$120
  Top 0.889: CON1.59 84.29,36.19 88.1,32.38 IC8.13
N$121
  Top 0.889: CON1.57 81.75,36.19 85.56,32.38 IC8.14
N$122
  Top 0.889: CON1.55 79.21,36.19 83.02,32.38 IC8.15
N$123
  Top 0.889: CON1.53 76.67,36.19 80.48,32.38 IC8.16
N$124
  Top 0.889: CON1.51 74.13,36.19 77.94,32.38 IC8.17
N$125
  Top 0.889: CON1.49 71.59,36.19 75.4,32.38 IC8.18
N$126
  Top 0.889: IC9.11 CON1.47
N$127
  Top 0.889: IC9.12 CON1.45
N$128
  Top 0.889: IC9.13 CON1.43
N$129
  Top 0.889: IC9.14 CON1.41
N$130
  Top 0.889: IC9.15 CON1.39
N$131
  Top 0.889: IC9.16 CON1.37
N$132
  Top 0.889: IC9.17 CON1.35
N$133
  Top 0.889: IC9.18 CON1.33
N$134
  Bottom 0.381: C4.1 R6.1 27.14,3.17 51.27,3.17 51.27,12.06 58.89,12.06 62.7,15.87 IC10.9
N$135
  Bottom 0.381: IC10.25 75.4,10.79 76.67,12.06 79.21,12.06 81.75,14.6 81.75,19.68 83.02,19.68 85.56,22.22 IC8.5

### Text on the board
Top: 5V 12V SCL SDA Gnd | Hi / Lo
Bottom: CAN Actor Driver Board V1.2
tOrigins: CAN Actor Driver Board | Hi / Lo | 5V 12V SCL SDA Gnd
